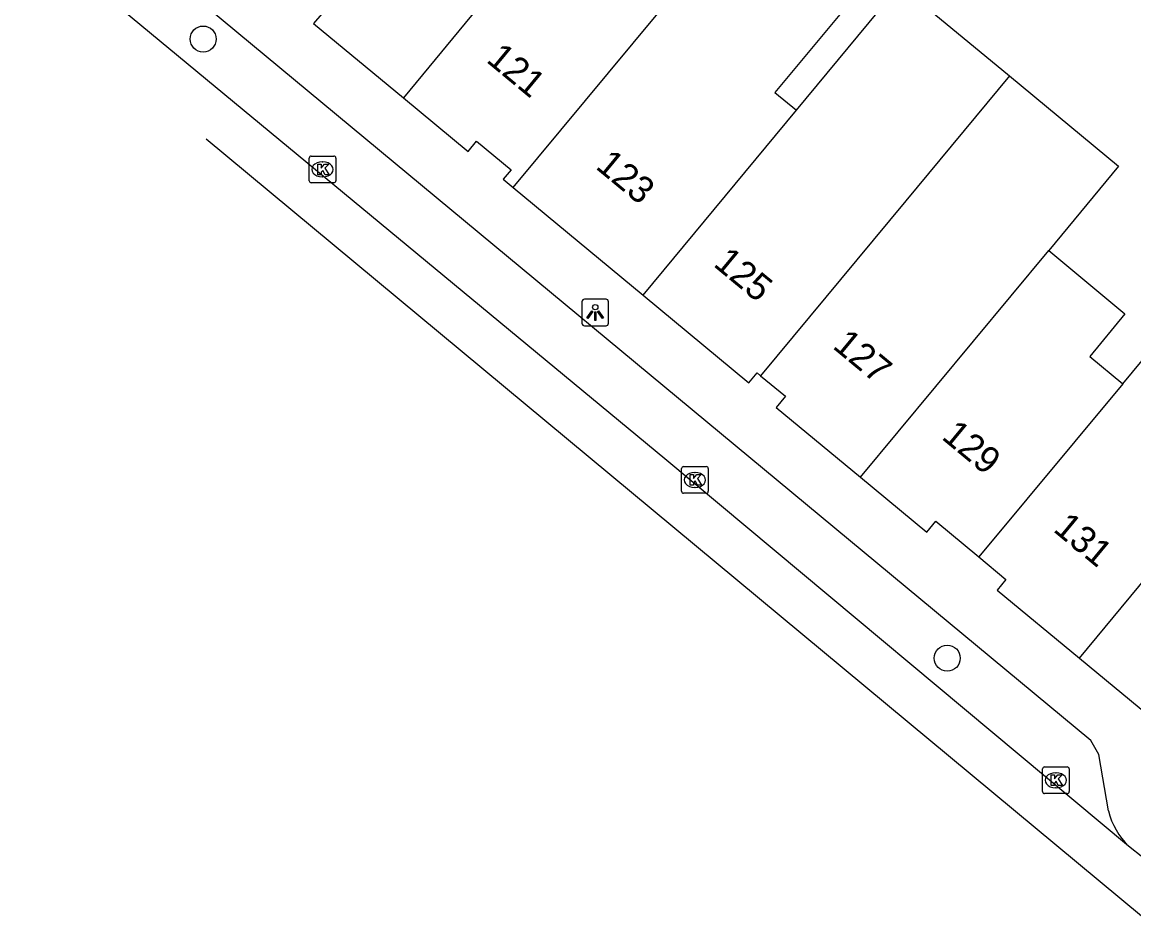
# Model space of a CAD drawing. Extents: x 162074 to 163034, y 381824 to 382557.
# Drawn here: x 162336.19 to 162377.96, y 381940.02 to 381973.59 of the extents above; entities that cross this region are included whole.
import ezdxf

# ---------------------------------------------------------------- set-up
doc = ezdxf.new("R2010")
doc.units = 0
for name, color, linetype in [('IMGEO_Boom', 7, 'Continuous'), ('IMGEO_Kolk', 7, 'Continuous'), ('IMGEO_Lichtpunt', 7, 'Continuous'), ('IMGEO_Pand', 7, 'Continuous'), ('IMGEO_Pand_nummerreeks', 7, 'Continuous'), ('IMGEO_Rijbaan_lokaal_gesloten', 7, 'Continuous'), ('IMGEO_Voetpad_open', 7, 'Continuous')]:
    doc.layers.add(name, color=color, linetype=linetype)

msp = doc.modelspace()

# ---------------------------------------------------------------- linework, layer by layer
at = {"layer": 'IMGEO_Boom'}
for centre in [(162342.989, 381972.955), (162370.946, 381949.697)]:
    msp.add_circle(centre, 0.489, dxfattribs=at)
at = {"layer": 'IMGEO_Kolk'}
for p, q in [((162346.975, 381967.632), (162346.975, 381968.484)), ((162347.05, 381968.558), (162347.902, 381968.558)), ((162347.463, 381968.338), (162347.488, 381968.338)), ((162347.976, 381968.484), (162347.976, 381967.632)), ((162347.902, 381967.558), (162347.05, 381967.558)), ((162347.486, 381967.778), (162347.461, 381967.778)), ((162360.967, 381955.965), (162360.967, 381956.817)), ((162361.042, 381956.891), (162361.894, 381956.891)), ((162361.455, 381956.671), (162361.48, 381956.671)), ((162361.968, 381956.817), (162361.968, 381955.965)), ((162361.478, 381956.111), (162361.453, 381956.111)), ((162361.894, 381955.891), (162361.042, 381955.891)), ((162374.527, 381944.683), (162374.527, 381945.535)), ((162374.602, 381945.609), (162375.454, 381945.609)), ((162375.015, 381945.389), (162375.04, 381945.389)), ((162375.528, 381945.535), (162375.528, 381944.683)), ((162375.038, 381944.829), (162375.013, 381944.829)), ((162375.454, 381944.609), (162374.602, 381944.609))]:
    msp.add_line(p, q, dxfattribs=at)
for points in [[(162346.975, 381967.632), (162346.975, 381968.484)], [(162347.05, 381968.558), (162347.902, 381968.558)], [(162347.296, 381968.258), (162347.419, 381968.258), (162347.419, 381968.107), (162347.549, 381968.258), (162347.713, 381968.258), (162347.567, 381968.107), (162347.72, 381967.858), (162347.568, 381967.858), (162347.483, 381968.022), (162347.419, 381967.955), (162347.419, 381967.858), (162347.296, 381967.858), (162347.296, 381968.258)], [(162347.976, 381968.484), (162347.976, 381967.632)], [(162347.902, 381967.558), (162347.05, 381967.558)], [(162360.967, 381955.965), (162360.967, 381956.817)], [(162361.042, 381956.891), (162361.894, 381956.891)], [(162361.288, 381956.591), (162361.411, 381956.591), (162361.411, 381956.44), (162361.541, 381956.591), (162361.705, 381956.591), (162361.559, 381956.44), (162361.712, 381956.191), (162361.56, 381956.191), (162361.475, 381956.355), (162361.411, 381956.288), (162361.411, 381956.191), (162361.288, 381956.191), (162361.288, 381956.591)], [(162361.968, 381956.817), (162361.968, 381955.965)], [(162361.894, 381955.891), (162361.042, 381955.891)], [(162374.527, 381944.683), (162374.527, 381945.535)], [(162374.602, 381945.609), (162375.454, 381945.609)], [(162374.848, 381945.309), (162374.971, 381945.309), (162374.971, 381945.158), (162375.101, 381945.309), (162375.265, 381945.309), (162375.119, 381945.158), (162375.272, 381944.909), (162375.12, 381944.909), (162375.035, 381945.073), (162374.971, 381945.006), (162374.971, 381944.909), (162374.848, 381944.909), (162374.848, 381945.309)], [(162375.528, 381945.535), (162375.528, 381944.683)], [(162375.454, 381944.609), (162374.602, 381944.609)]]:
    msp.add_lwpolyline(points, dxfattribs=at)
for centre, start, end in [((162347.052, 381968.482), 91.552, 178.448), ((162347.052, 381968.482), 91.552, 178.448), ((162347.9, 381968.482), 1.552, 88.448), ((162347.9, 381968.482), 1.552, 88.448), ((162347.052, 381967.634), 181.552, 268.448), ((162347.052, 381967.634), 181.552, 268.448), ((162347.9, 381967.634), 271.552, 358.448), ((162347.9, 381967.634), 271.552, 358.448), ((162361.044, 381956.815), 91.552, 178.448), ((162361.044, 381956.815), 91.552, 178.448), ((162361.892, 381956.815), 1.552, 88.448), ((162361.892, 381956.815), 1.552, 88.448), ((162361.044, 381955.967), 181.552, 268.448), ((162361.044, 381955.967), 181.552, 268.448), ((162361.892, 381955.967), 271.552, 358.448), ((162361.892, 381955.967), 271.552, 358.448), ((162374.604, 381945.533), 91.552, 178.448), ((162374.604, 381945.533), 91.552, 178.448), ((162375.452, 381945.533), 1.552, 88.448), ((162375.452, 381945.533), 1.552, 88.448), ((162374.604, 381944.685), 181.552, 268.448), ((162374.604, 381944.685), 181.552, 268.448), ((162375.452, 381944.685), 271.552, 358.448), ((162375.452, 381944.685), 271.552, 358.448)]:
    msp.add_arc(centre, 0.0765, start, end, dxfattribs=at)
for centre, major_axis, ratio, start_param, end_param in [((162347.462, 381968.058), (-0.387, 0.002), 0.722429, 4.712389, 7.853982), ((162347.487, 381968.058), (-0.39, 0.002), 0.717154, 1.570796, 4.712389), ((162361.454, 381956.391), (-0.387, 0.002), 0.722429, 4.712389, 7.853982), ((162361.479, 381956.391), (-0.39, 0.002), 0.717154, 1.570796, 4.712389), ((162375.014, 381945.109), (-0.387, 0.002), 0.722429, 4.712389, 7.853982), ((162375.039, 381945.109), (-0.39, 0.002), 0.717154, 1.570796, 4.712389)]:
    msp.add_ellipse(centre, major_axis=major_axis, ratio=ratio, start_param=start_param, end_param=end_param, dxfattribs=at)
at = {"layer": 'IMGEO_Lichtpunt'}
for p, q in [((162357.224, 381963.085), (162357.224, 381962.278)), ((162357.224, 381963.085), (162357.224, 381962.278)), ((162358.126, 381963.18), (162357.318, 381963.18)), ((162358.126, 381963.18), (162357.318, 381963.18)), ((162358.22, 381962.278), (162358.22, 381963.085)), ((162358.22, 381962.278), (162358.22, 381963.085)), ((162357.318, 381962.184), (162358.126, 381962.184)), ((162357.318, 381962.184), (162358.126, 381962.184))]:
    msp.add_line(p, q, dxfattribs=at)
for points in [[(162357.598, 381962.749), (162357.637, 381962.721), (162357.449, 381962.459), (162357.411, 381962.486), (162357.598, 381962.749)], [(162357.7, 381962.701), (162357.747, 381962.701), (162357.747, 381962.379), (162357.7, 381962.379), (162357.7, 381962.701)], [(162357.81, 381962.721), (162357.848, 381962.748), (162358.035, 381962.486), (162357.996, 381962.458), (162357.81, 381962.721)]]:
    msp.add_lwpolyline(points, dxfattribs=at)
msp.add_circle((162357.723, 381962.883), 0.0994, dxfattribs=at)
for centre, start, end in [((162357.318, 381963.085), 90, 180), ((162357.318, 381963.085), 90, 180), ((162358.126, 381963.085), 0, 90), ((162358.126, 381963.085), 0, 90), ((162357.318, 381962.278), 180, 270), ((162357.318, 381962.278), 180, 270), ((162358.126, 381962.278), 270, 0), ((162358.126, 381962.278), 270, 360)]:
    msp.add_arc(centre, 0.0946, start, end, dxfattribs=at)
at = {"layer": 'IMGEO_Pand'}
for points in [[(162354.643, 381967.372), (162363.656, 381978.23)], [(162356.335, 381977.804), (162350.514, 381970.745)], [(162370.033, 381977.658), (162367.72, 381974.865), (162364.475, 381970.946), (162365.281, 381970.278)], [(162365.281, 381970.278), (162369.166, 381974.973)], [(162369.166, 381974.973), (162373.282, 381971.567)], [(162346.715, 381974.514), (162347.448, 381973.907), (162347.142, 381973.537), (162350.514, 381970.745)], [(162373.282, 381971.567), (162369.388, 381966.878), (162363.931, 381960.306)], [(162373.282, 381971.567), (162377.383, 381968.174), (162374.762, 381965.007)], [(162350.514, 381970.745), (162352.944, 381968.733), (162353.264, 381969.12), (162354.562, 381968.046), (162354.264, 381967.685), (162354.643, 381967.372)], [(162359.517, 381963.336), (162365.281, 381970.278)], [(162354.643, 381967.372), (162359.517, 381963.336)], [(162367.692, 381956.491), (162374.762, 381965.007)], [(162374.762, 381965.007), (162377.625, 381962.637), (162376.299, 381961.035), (162377.54, 381960.007)], [(162359.517, 381963.336), (162363.494, 381960.043), (162363.801, 381960.414), (162363.931, 381960.306)], [(162377.54, 381960.007), (162379.844, 381962.782), (162383.946, 381959.377), (162381.646, 381956.606)], [(162363.931, 381960.306), (162364.865, 381959.533), (162364.52, 381959.117), (162367.692, 381956.491)], [(162377.54, 381960.007), (162372.135, 381953.497)], [(162375.911, 381949.698), (162381.646, 381956.606)], [(162367.692, 381956.491), (162370.179, 381954.431), (162370.516, 381954.837), (162372.135, 381953.497)], [(162372.135, 381953.497), (162373.154, 381952.653), (162372.824, 381952.254), (162375.911, 381949.698)], [(162375.911, 381949.698), (162378.804, 381947.303), (162379.189, 381947.768), (162380.402, 381946.763)]]:
    msp.add_lwpolyline(points, dxfattribs=at)
at = {"layer": 'IMGEO_Rijbaan_lokaal_gesloten'}
for points in [[(162377.76, 381942.629), (162360.336, 381957.182), (162336.192, 381977.174)], [(162343.107, 381969.212), (162378.252, 381940.019)], [(162379.368, 381941.362), (162377.76, 381942.629)]]:
    msp.add_lwpolyline(points, dxfattribs=at)
at = {"layer": 'IMGEO_Voetpad_open'}
msp.add_lwpolyline([(162377.001, 381943.955), (162376.642, 381946.078), (162376.347, 381946.606), (162338.377, 381978.091)], dxfattribs=at)
msp.add_arc((162379.794, 381944.674), 2.884, 194.4275, 225.146, dxfattribs=at)

# ---------------------------------------------------------------- texts
at = {"layer": 'IMGEO_Pand_nummerreeks'}
for s, rotation, p in [('121', 320.3972, (162353.59, 381972.121)), ('123', 320.3857, (162357.696, 381968.117)), ('125', 320.3592, (162362.123, 381964.451)), ('127', 320.375, (162366.601, 381961.368)), ('129', 320.3786, (162370.698, 381957.958)), ('131', 320.3786, (162374.891, 381954.486))]:
    msp.add_text(s, height=1, rotation=rotation, dxfattribs=at).set_placement(p)

doc.saveas('drawing.dxf')
